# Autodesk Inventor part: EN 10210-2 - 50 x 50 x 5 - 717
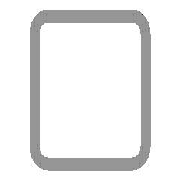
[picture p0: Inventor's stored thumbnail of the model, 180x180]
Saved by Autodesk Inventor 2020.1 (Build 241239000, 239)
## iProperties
Created: 2019-01
Part Number: EN 10210-2 - 50 x 50 x 5 - 717
Material: Stahl, weich
Description: Rohrleitung
Document SubType Name: Modeling
Standard: DIN
Designer: lutzd
Standard Revision: 2006-07
Standards Organization: DIN
Language: de-DE
Size Designation: 50 x 50 x 5
Categories: <MemberInstance><Categories><Category DisplayName="Profile" InternalName="089c4875-fa83-4c05-b084-43b9cc11f5ed" Mnemonic="GRDR"><CategoryParameter DisplayName="
Stock Number: 50 x 50 x 5
Mass: 4910.53 g
Surface Area: 2445.84 cm^2
Volume: 625.546 cm^3
Density: 7.85 g/cm^3
Appearance: Halbpoliert
_CCFamilyMember: 16
_CCFamilyDisplayName: DIN EN 10210-2 (USAS B17.1 quadratisch) - Rohrleitung — In Klammern angegebene Größen wurden aufgehoben
_FrameMemberDoc: Frame Member File
_Version: 15.0.0
_GetPNFromCC: 1
G_L: 717,000 mm
G_W: 50,000 mm
G_H: 50,000 mm
Dimensions: 50x50x717 mm
Mass: 4,911 kg
+B50F23D3-110B-458B-B93C-BEDBAF8228A3+SCHNITTDETAIL1: Schnittwinkel 90,00 grd
+FA356EBA-E7B4-4F83-B9EA-22CB517C3328+SCHNITTDETAIL2: Schnittwinkel 90,00 grd
DocNumber: ADSK-014151
Folder: .
IsCustomPart: 1
Title: Profil-Bauteil
Author: lutzd
Revision Number: -
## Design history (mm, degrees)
node "Startebene"
node "Endebene"
sketch "Skizze"
  geometry: L1 (-25, -17.5)-(-25, 17.5); L2 (-17.5, 25)-(17.5, 25); L3 (25, 17.5)-(25, -17.5); L4 (17.5, -25)-(-17.5, -25); L5 (-15, 20)-(15, 20); L6 (20, 15)-(20, -15); L7 (15, -20)-(-15, -20); L8 (-20, -15)-(-20, 15); L9 (0, 37.175)-(0, -37.175) reference; L10 (-37.175, 0)-(37.175, 0) reference; A1 r 7.5 centre (-17.5, -17.5) between (-25, -17.5) and (-17.5, -25); A2 r 7.5 centre (-17.5, 17.5) between (-17.5, 25) and (-25, 17.5); A3 r 7.5 centre (17.5, 17.5) between (25, 17.5) and (17.5, 25); A4 r 7.5 centre (17.5, -17.5) between (17.5, -25) and (25, -17.5); A5 r 5 centre (-15, -15) between (-20, -15) and (-15, -20); A6 r 5 centre (-15, 15) between (-15, 20) and (-20, 15); A7 r 5 centre (15, 15) between (20, 15) and (15, 20); A8 r 5 centre (15, -15) between (15, -20) and (20, -15)
  constraints: 16 end point, 16 point on circle, 16 tangent, 8 centre point, 6 equal radius, 4 parallel, 2 perpendicular, 2 other
  dimensions: "d7" = 7.5 radius of A1 (= G_IR); "d10" = 50 distance between parallel lines of L2 L4 (= G_H); "d11" = 50 distance between parallel lines of L1 L3 (= G_W); "d12" = 5 distance between parallel lines of L3 L6 (= G_T); "d15" = 25 distance between parallel lines of L2 L10 (= 0.5 x d10); "d16" = 25 distance between parallel lines of L9 L3 (= 0.5 x d11); "d19" = 5 radius of A5 (= G_T); "d20" = 5 distance between parallel lines of L4 L7 (= G_T)
extrude "Körper" new body sketch "Skizze" stored distance "d3" = 717 (= G_L); taper "d4" = 0 deg
node "Driven Length"
  sketch "Sketch3"
    geometry: L1 (0, 0)-(10, 0) reference
    constraints: 2 end point, 1 horizontal
  workplane "Work Plane3"
  sketch "Sketch4"
    geometry: L1 (-2, 50)-(12, 50) reference; L2 (-2, 767)-(12, 767) reference
    dimensions: "d18" = 717 distance between parallel lines of L1 L2 (derived)
workplane "Arbeitsebene4"
feature "Trennen1"
workplane "Arbeitsebene5"
feature "Trennen2"
sketch "Skizze5"
  geometry: L1 (717, 35)-(717, 0) reference; L2 (717, 17.5)-(108.5, 17.5); 4 further points
  constraints: 2 end point, 2 point on line, 1 coincident, 1 horizontal, 1 midpoint
  dimensions: "d21" = 284.5 distance from line of L1 point (432.5, 17.5); "d22" = 162 distance of point (270.5, 17.5) point (432.5, 17.5); "d23" = 162 distance of point (108.5, 17.5) point (270.5, 17.5) (= d22)
hole "Bohrung1" sketch "Skizze5" at (108.5, 17.5), (270.5, 17.5), (432.5, 17.5) diameter "d24" = 6.647; stored, may be unused: countersink angle "d28" = 90 deg, drill point angle "d30" = 118 deg; dims "d25" = 16, "d26" = 4, "d27" = 2, "d29" = 22.2
body "Solid1"
other parameters: "G_W" = 50 [user parameter; used in 1 equation term], "G_H" = 50 [user parameter; used in 1 equation term], "G_T" = 5 [user parameter; used in 3 equation terms], "G_IR" = 7.5 [user parameter; used in 1 equation term], "G_L" = 717 (= d18) [user parameter; used in 1 equation term], "G_OFFSET_END" = -25 [user parameter; used in 1 equation term], "d14" = 767 (= G_OFFSET_END + B_L), "B_L" = 792 [user parameter; used in 1 equation term], "d17" = 90 deg
